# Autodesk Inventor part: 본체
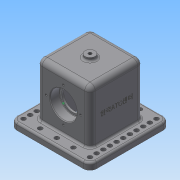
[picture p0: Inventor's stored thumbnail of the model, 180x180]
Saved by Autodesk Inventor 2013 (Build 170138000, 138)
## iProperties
Created: 2018-11
Part Number: 본체
Material: 일반
Document SubType Name: Modeling
Designer: Administrator
Density: 1 g/cm^3
Author: Administrator
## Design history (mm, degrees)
sketch "스케치1"
  geometry: 1 further point
sketch "스케치2"
  geometry: L1 (-40, 40)-(40, 40); L2 (40, 40)-(40, -40); L3 (40, -40)-(-40, -40); L4 (-40, -40)-(-40, 40); L5 (-40, 40)-(40, -40); L6 (40, 40)-(-40, -40); 1 further point
  constraints: 12 end point, 2 midpoint, 2 parallel, 1 horizontal, 1 perpendicular
  dimensions: "d0" = 80 distance of L1.start L1.end; "d2" = 80 distance of L1.end L2.end
extrude "돌출1" new body sketch "스케치2" distance "d3" = 80; taper "d4" = 0 deg
node "작업 평면1"
sketch "스케치3"
  geometry: L1 (-40, 80)-(40, 80) reference; C1 r 7.5 at (0, 40); 1 further point
  constraints: 1 centre point, 1 vertical alignment
  dimensions: "d6" = 15 diameter of C1; "d8" = 40 distance from line of C1.centre L1
extrude "돌출2" join sketch "스케치3" stored distance "d9" = 80; taper "d10" = 0 deg
node "작업 평면2"
sketch "스케치4"
  geometry: L1 (60, -20)-(-60, -20); L2 (-60, -20)-(-60, 100); L3 (-60, 100)-(60, 100); L4 (60, 100)-(60, -20); L5 (60, -20)-(-60, 100); L6 (-60, -20)-(60, 100); C1 r 7.5 at (0, 40) reference; 1 further point
  constraints: 12 end point, 2 midpoint, 2 parallel, 1 horizontal, 1 perpendicular
  dimensions: "d12" = 120 distance between parallel lines of L1 L3; "d14" = 120 distance between parallel lines of L4 L2
extrude "돌출3" join sketch "스케치4" distance "d15" = 10; taper "d16" = 0 deg
sketch "스케치5"
  geometry: L1 (-60, 100)-(-60, -20) reference; L2 (30, 63)-(-30, 63); L3 (-30, 63)-(-30, 17); L4 (-30, 17)-(30, 17); L5 (30, 17)-(30, 63); L6 (30, 63)-(-30, 17); L7 (-30, 63)-(30, 17); C1 r 7.5 at (0, 40) reference; 1 further point
  constraints: 12 end point, 2 midpoint, 2 parallel, 1 horizontal, 1 perpendicular
  dimensions: "d17" = 46 distance of L4.end L2.start; "d19" = 60 distance of L2.start L2.end
extrude "돌출4" cut sketch "스케치5" distance "d20" = 80; taper "d21" = 0 deg
sketch "스케치10"
  geometry: C1 r 7.5 at (0, 0) reference; 2 further points
  constraints: 1 coincident
hole "구멍1" sketch "스케치10" at (0, 0) diameter "d38" = 4.917; stored, may be unused: countersink angle "d42" = 90 deg, drill point angle "d44" = 118 deg; dims "d39" = 6, "d40" = 4, "d41" = 2, "d43" = 30
fillet "모깎기1" dims "d69" = 10
sketch "스케치13" dims "d77" = 10, "d85" = 10
  geometry: L1 (-60, 90)-(-60, -10) reference; L2 (60, -10)-(60, 90) reference; C1 r 3.3 at (-50, -10); C2 r 3.3 at (-50, 0); C3 r 3.3 at (-50, 10); C4 r 3.3 at (-50, 20); C5 r 3.3 at (-50, 30); C6 r 3.3 at (-50, 40); C7 r 3.3 at (-50, 50); C8 r 3.3 at (-50, 60); C9 r 3.3 at (-50, 70); C10 r 3.3 at (-50, 80); C11 r 3.3 at (-50, 90); C12 r 3.3 at (50, -10); C13 r 3.3 at (50, 0); C14 r 3.3 at (50, 10); C15 r 3.3 at (50, 20); C16 r 3.3 at (50, 30); C17 r 3.3 at (50, 40); C18 r 3.3 at (50, 50); C19 r 3.3 at (50, 60); C20 r 3.3 at (50, 70); C21 r 3.3 at (50, 80); C22 r 3.3 at (50, 90); C23 r 3.3 at (-25, -10); C24 r 3.3 at (0, -10); C25 r 3.3 at (25, -10); C26 r 3.3 at (-25, 90); C27 r 3.3 at (0, 90); C28 r 3.3 at (25, 90); A1 r 10 centre (-50, 90) between (-50, 100) and (-60, 90) reference; A2 r 10 centre (-50, -10) between (-60, -10) and (-50, -20) reference; A3 r 10 centre (50, -10) between (50, -20) and (60, -10) reference; 1 further point
  constraints: 28 centre point, 7 horizontal alignment, 4 equal radius, 2 coincident, 2 vertical, 40 other
  dimensions: "d70" = 6.6 diameter of C1; "d74" = 10 distance of C1.centre C2.centre; "d79" = 6.6 diameter of C12; "d82" = 10 distance of C12.centre C13.centre; "d87" = 25 distance of C23.centre A2.centre; "d89" = 25 distance of C24.centre C23.centre; "d91" = 25 distance of C26.centre A1.centre; "d93" = 25 distance of C27.centre C26.centre; "d94" = 25 distance of C28.centre C27.centre; "d95" = 25 distance of C25.centre C24.centre; "d96" = 6.6 diameter of C25; "d97" = 6.6 diameter of C27
extrude "돌출9" cut sketch "스케치13" stored distance "d98" = 3; taper "d99" = 0 deg
fillet "모깎기2" dims "d100" = 8
fillet "모깎기3" dims "d101" = 3
fillet "모깎기5" dims "d106" = 3
node "작업 평면3"
node "작업 평면4"
sketch "스케치14"
  geometry: L1 (50, -50)-(-50, -50) reference; L2 (-40, 32)-(-40, -37) reference; C1 r 20 at (0, -2); 1 further point
  constraints: 1 centre point
  dimensions: "d109" = 48 distance from line of L1 C1.centre; "d110" = 40 distance from line of L2 C1.centre; "d111" = 40 diameter of C1
extrude "돌출10" cut sketch "스케치14" distance "d112" = 14; taper "d113" = 0 deg
sketch "스케치15"
  geometry: C1 r 20 at (0, 0) reference; C2 r 16.5 at (0, 0); 1 further point
  constraints: 1 centre point, 1 coincident
  dimensions: "d114" = 33 diameter of C2
extrude "돌출11" cut sketch "스케치15" distance "d116" = 3; taper "d117" = 0 deg
sketch "스케치16"
  geometry: L1 (-50, 50)-(50, 50) reference; L2 (40, -32)-(40, 37) reference; C1 r 20 at (0, 2); 1 further point
  constraints: 1 centre point
  dimensions: "d118" = 48 distance from line of L1 C1.centre; "d119" = 40 distance from line of L2 C1.centre; "d120" = 40 diameter of C1
extrude "돌출12" cut sketch "스케치16" distance "d121" = 14; taper "d122" = 0 deg
sketch "스케치17"
  geometry: C1 r 20 at (0, 0) reference; C2 r 16.5 at (0, 0); 1 further point
  constraints: 1 centre point, 1 coincident
  dimensions: "d123" = 33 diameter of C2
extrude "돌출13" cut sketch "스케치17" distance "d125" = 3; taper "d126" = 0 deg
sketch "스케치18" dims "d127" = 52
  geometry: C1 r 20 at (0, -2) reference; 3 further points
  constraints: 2 vertical alignment, 1 coincident, 2 other
hole "구멍4" sketch "스케치18" at (0, 24) diameter "d129" = 3.242; stored, may be unused: countersink angle "d133" = 90 deg, drill point angle "d135" = 118 deg; dims "d130" = 8, "d131" = 4, "d132" = 2, "d134" = 10
sketch "스케치19" dims "d139" = 52
  geometry: C1 r 20 at (0, 2) reference; 3 further points
  constraints: 2 vertical alignment, 1 coincident, 2 other
hole "구멍5" sketch "스케치19" at (0, -24) diameter "d141" = 3.242; stored, may be unused: countersink angle "d145" = 90 deg, drill point angle "d147" = 118 deg; dims "d142" = 8, "d143" = 4, "d144" = 2, "d146" = 10
sketch "스케치20"
  geometry: L1 (82, 82)-(82, -18) reference; L2 (0, -8)-(69, -8) reference; 2 further points
  constraints: 1 other
  dimensions: "d151" = 48 distance from line of L1 point (34, 32); "d152" = 40 distance from line of L2 point (34, 32)
extrude "돌출14" join sketch "스케치20" distance "d153" = 0.5; taper "d154" = 0 deg
chamfer "모따기2" distance "d155" = 1; stored, may be unused: second distance "d156" = 2, angle "d157" = 45 deg
fillet "모깎기6" dims "d158" = 0.6
node "솔리드1"
pattern_circular "원형 패턴3" dims angle "d137" = 360 deg
pattern_circular "원형 패턴4" dims angle "d149" = 360 deg
other parameters: "d5" = 45, "d107" = -48, "d108" = -48
